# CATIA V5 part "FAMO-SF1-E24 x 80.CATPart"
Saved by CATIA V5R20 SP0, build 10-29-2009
Part number: FAMO-SF1-E24 x 80
Definition: NONE
Nomenclature: FAMO-SF1-E24 x 80
Source: Unknown
Description: FAMO-SF1-E24 x 80
Bounding box of the stored display mesh (mm): x -57 to 23, y -22 to 22, z -22 to 22
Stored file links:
  C:\Users\Utente\Desktop\IO LAVORO\3D X SITO CF\X SITO\FAMO\FAMO-SF1-E24 x 80.CATPart

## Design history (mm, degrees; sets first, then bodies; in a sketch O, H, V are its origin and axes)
Body1 "FAMO-SF1-E24 x 80" (main body)
  Solid1: solid without history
